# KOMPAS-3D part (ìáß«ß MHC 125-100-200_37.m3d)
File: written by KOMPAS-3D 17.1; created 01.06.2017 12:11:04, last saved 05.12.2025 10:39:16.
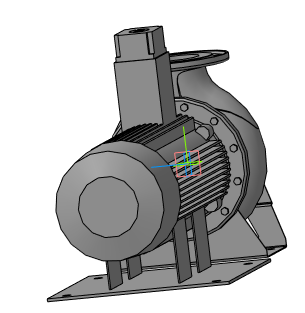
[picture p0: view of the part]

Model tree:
1. Операция без истории:1

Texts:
  ООО АДЛ ГРУПП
